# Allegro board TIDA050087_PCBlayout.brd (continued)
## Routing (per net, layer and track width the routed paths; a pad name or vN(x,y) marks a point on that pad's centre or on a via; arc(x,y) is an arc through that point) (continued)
N116698763: length 1
  TOP w0.104: U201.A8 v1(42.32,36.55)
  BOTTOM w0.112: R211.2 42.3,36.12 42.3,36.53 v1(42.32,36.55)
N116700633: length 6
  TOP w0.112: TP805.1 48.77,56.43 v1(49.19,56.86)
  BOTTOM w0.112: v1(49.19,56.86) 53.14,56.86 53.48,56.52 J802.51
N116701055: length 1.7
  TOP w0.254: U913.2 2.84,4.02 R1033.2
N116701070: length 1.5
  TOP w0.254: R1032.2 2.34,3.54 U913.1
N116772045: length 2.5
  TOP w0.381: 26.04,3.37 U919.2
N116772074: length 3
  TOP w0.203: U919.5 26.04,8.4 25.97,8.47 ; 25.97,8.47 R1088.1 26.14,8.63 R1087.2 ; 25.97,8.47 25.95,8.44 C719.2
N116772436: length 5.6
  TOP w0.112: R1089.2 10.01,16.63 v1(11.31,16.63) ; U920.3 10.5,19.04 10.42,19.12 R1090.1 10.5,19.45 10.51,19.46 v1(10.88,19.46)
  BOTTOM w0.112: v1(11.31,16.63) 11.31,17.89 10.9,18.3 10.9,19.44 v1(10.88,19.46)
N116861023: length 2.3
  BOTTOM w0.112: Q903.3 40.07,12.25 R717.1 40.44,10.89 R724.1
N116861029: length 2.8
  BOTTOM w0.112: Q902.3 35.95,10.01 35.95,8.85 35.66,8.55 R725.1 35.22,8.55 35.01,8.77 R719.1
N116892698: length 3.8
  TOP w0.112: TP969.1 24.85,20.84 v1(25.3,20.38) 26.17,19.51 U701.16
  BOTTOM w0.112: R1097.2 25.02,20.66 v1(25.3,20.38)
N116924893: length 5.1
  TOP w0.112: v1(32.52,14.08) 32.37,14.23 30.98,14.23 29.5,15.72 U701.1
  BOTTOM w0.112: R1091.1 33.16,14.87 32.52,14.23 v1(32.52,14.08)
N116924896: length 5.1
  TOP w0.112: v1(32.19,13.62) 32.19,13.65 31.91,13.93 31.74,13.93 31.74,13.93 30.95,13.93 29.57,15.31 29.56,15.31 29.33,15.54 U701.32
  BOTTOM w0.112: R1092.1 32.93,13.62 v1(32.19,13.62)
N116924899: length 4.6
  TOP w0.112: U701.24 25.26,16.07 24.62,15.42 24.62,14.49 25.02,14.08 v1(25.02,13.44)
  BOTTOM w0.112: v1(25.02,13.44) 24.59,13.01 24.59,12.8 R1093.1
N116925021: length 7.9
  TOP w0.112: v1(31.02,13.52) 29.47,15.07 28.81,15.07 28.8,15.08 28.79,15.08 28.57,15.3 U701.31
  BOTTOM w0.112: v1(31.02,13.52) 31.02,12.48 31.65,11.84 R1102.2 R1099.1
N116939248: length 4.9
  TOP w0.112: U701.8 29.68,18.87 30.11,19.31 v1(30.11,20.12)
  BOTTOM w0.112: v1(30.11,20.12) 30.17,20.18 R1064.2 30.17,21.03 30.82,21.67 32.02,21.67 R1094.2
N116980775: length 5.6
  TOP w0.112: U701.17 25.47,18.87 25.23,19.11 v1(25.23,19.79) 24.59,20.43 24.59,20.86 TP970.1
  BOTTOM w0.112: R1096.2 24.29,20.73 v1(25.23,19.79)
N116981199: length 1.7
  TOP w0.112: v1(24.97,7.63) 25.05,7.71 25.38,7.71 25.54,7.54 U919.6
  BOTTOM w0.112: R1098.1 24.51,7.63 v1(24.97,7.63)
N117032871: length 2.4
  TOP w0.381: U905.4 63.41,7.78 R1104.2 63.37,7.75 62.56,7.75 R1103.1

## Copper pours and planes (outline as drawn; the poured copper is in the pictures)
GND on TOP: 67.6,27.56 69.64,27.56 69.85,27.34 69.85,27.07 69.76,26.97 69.36,26.97 69.25,26.86 69.25,26.42 69.17,26.34 66.6,26.34 66.3,26.63 66.3,27.12 66.44,27.26 67.31,27.26
GND on TOP: 63.76,6.03 63.91,5.87 63.91,5.19 63.76,5.04 62.87,5.04 62.77,4.93 62.77,3.66 62.69,3.59 62.24,3.59 62.16,3.66 62.16,4.78 61.88,5.06 58.02,5.06 57.84,5.24 57.84,5.95 57.92,6.03
GND on TOP: 53.15,40.42 54.8,40.42 54.89,40.33 54.89,40.02 54.79,39.92 54.55,39.92 54.35,39.73 54.35,37.85 54.87,37.33 54.87,37.14 54.73,37 53.22,37 53.09,37.12 53.09,37.31 53.21,37.43 53.8,37.43 53.98,37.61 53.98,39.03 53.91,39.09 53.91,39.24 53.96,39.29 53.96,39.8 53.98,39.81 53.98,39.86 53.87,39.96 53.22,39.96 53.15,40.03
GND on TOP: 62.26,11.85 64.6,11.85 64.76,11.7 64.76,7.75 64.76,7.74 64.59,7.57 63.92,7.57 63.86,7.63 63.86,8.14 63.68,8.31 62.81,8.31 62.68,8.44 62.68,10.23 62.22,10.69 62.22,11.81
GND on TOP: 8.59,11.38 12.2,11.38 12.52,11.06 12.52,9.64 12.17,9.29 8.67,9.29 8.35,9.61 8.35,11.13
GND on TOP: 26.7,22.89 28.38,22.89 28.76,22.51 28.76,21.55 28.71,21.5 26.73,21.5 26.55,21.67 26.55,22.74
GND on TOP: 50.71,40.44 52.3,40.44 52.34,40.39 52.34,40.11 52.3,40.06 51.68,40.06 51.47,39.85 51.47,37.59 51.62,37.43 52.15,37.43 52.31,37.27 52.31,37.08 52.25,37.01 50.78,37.01 50.61,37.18 50.61,37.34 50.74,37.47 51,37.47 51.13,37.59 51.13,39.76 50.94,39.95 50.66,39.95 50.58,40.04 50.58,40.31
GND on TOP: 2.69,8.09 3.96,8.09 4.75,7.3 4.75,4.89 4.31,4.45 3.79,4.45 3.71,4.54 3.71,5.38 3.57,5.52 1.85,5.52 1.69,5.68 1.69,6.96 1.95,7.21 2.45,7.21 2.64,7.4 2.64,8.04
GND on TOP: 0.49,60.6 73.23,60.6 73.23,50.85 71.69,50.85 65.18,57.37 61.75,57.37 59.02,60.09 41.84,60.09 40.07,58.33 38.66,58.33 36.87,60.12 11.79,60.12 10.89,59.21 8.21,59.21 7.32,60.1 7.32,60.12 2.63,60.12 1.19,58.67 1.19,51.47 1.89,50.77 1.89,46.98 1.19,46.29 1.19,26.31 1.86,25.64 1.86,22.49 1.02,21.65 1.02,12.3 1.61,11.72 1.61,8.24 1.19,7.82 1.19,1.8 1.11,1.71 3.52,1.71 3.84,2.04 5.33,2.04 5.89,2.6 5.89,3.45 5.92,3.48 7.49,3.48 8.16,2.81 8.16,0.51 0.49,0.51
GND on TOP: 48.09,42.93 52.27,42.93 52.39,42.81 52.39,42.61 52.28,42.5 49.16,42.5 48.98,42.32 48.98,35.05 49.13,34.9 50.27,34.9 50.34,34.83 50.34,34.48 50.31,34.45 48.62,34.45 48.45,34.62 48.45,42.35 48.27,42.53 48.07,42.53 48,42.6 48,42.83
GND on TOP: 20.83,12.2 20.83,12.83 21.21,13.22 22.15,13.22 22.79,13.85 24.64,13.85 24.69,13.8 24.69,12.1 24.54,11.95 21.09,11.95
GND on TOP: 27.84,7.32 27.87,7.35 27.87,7.47 27.9,7.5 29.22,7.5 29.27,7.45 29.27,6.38 29.24,6.36 27.9,6.36 27.87,6.33 27.03,6.33 27.01,6.36 25.74,6.36 25.71,6.33 25.71,5.54 25.66,5.49 25.28,5.49 25.15,5.62 23.6,5.62 23.5,5.72 23.5,7.27 23.63,7.4 24.64,7.4 25.15,6.89 27.64,6.89 27.84,7.09
GND on TOP: 30.87,11.95 31.37,11.44 33.23,11.44 33.23,11.46 33.46,11.69 33.46,13.14 33.37,13.23 29.69,13.23 29.55,13.09 29.55,12.07 29.67,11.95
GND on TOP: 25.56,20.58 25.56,20.17 25.91,19.82 26.32,19.82 26.37,19.77 26.7,19.77 26.75,19.82 26.75,19.95 26.14,20.56 26.07,20.56 25.96,20.66 25.96,21.17 25.56,21.17 25.51,21.11 25.51,20.63
GND on TOP: 41.4,13.53 41.84,13.09 41.84,12.3 41.1,11.56 35.87,11.56 35.49,11.95 35.49,13.47 35.55,13.53
GND on TOP: 66.8,23.43 68.84,23.43 69,23.27 69.95,23.27 70.18,23.04 70.18,19.63 69.97,19.43 68.9,19.43 68.56,19.77 68.56,21.02 68.16,21.43 67.06,21.43 66.74,21.75 66.74,23.36
GND on TOP: 72.23,17.68 73.23,17.68 73.23,0.51 69.15,0.51 68.76,0.9 68.76,14.46 69.14,14.84 69.87,14.85 71.36,14.85 71.76,15.25 71.76,15.83 71.8,15.87 71.8,17.26
GND on TOP: 12.66,20.12 12.66,18.75 12.55,18.65 11.49,18.65 10.93,18.09 10.61,18.41 11.11,18.9 11.11,19.21 11.21,19.31 11.21,19.72 11.08,19.84 10.65,19.84 10.62,19.82 10.19,19.82 10.08,19.7 10.08,19.1 9.78,18.8 8.9,18.8 8.62,19.08 8.62,20.3 9.01,20.7 12.08,20.7
GND on BOTTOM: 23.4,15.91 23.37,15.91 23.25,16.03 22.36,16.03 21.75,15.42 21.75,15.4 21.72,15.37 21.72,14.28 21.93,14.08 23.22,14.08 23.4,14.26
GND on BOTTOM: 0.49,60.6 73.23,60.6 73.23,45.89 66.86,45.89 65.42,44.46 65.42,44.18 64.17,44.18 63.32,45.04 60.87,45.04 59.75,43.91 59.75,43.29 59.12,42.67 58.08,42.67 56.83,43.91 55.43,43.91 54.08,45.27 54.08,50.55 55.2,51.68 58.5,51.68 60.56,53.74 60.56,58.51 59.06,60.01 43.04,60.01 40.72,57.69 39.17,57.69 39,57.86 33.06,57.86 32.79,58.13 21.99,58.13 18.45,54.6 12.86,54.6 12.57,54.89 8.71,54.89 8.72,54.89 12.57,54.89 12.7,54.75 12.79,54.75 12.87,54.74 12.95,54.69 13.04,54.6 13.08,54.6 13.12,54.63 13.11,54.68 12.31,55.49 11.68,55.49 7.36,59.82 6.71,59.82 6.71,59.73 6.75,59.72 6.81,59.69 6.86,59.64 6.92,59.62 6.99,59.63 7.08,59.68 7.19,59.7 7.42,59.6 7.52,59.37 7.47,59.19 7.33,59.07 7.3,59.05 7.3,58.67 7.83,58.13 7.88,58.06 7.9,57.97 7.9,55.43 8.54,54.79 8.59,54.78 8.62,54.81 8.63,54.82 8.63,53.37 13.27,48.73 13.27,46.17 12.84,45.74 7.15,45.74 5.36,43.95 2.3,43.95 0.49,45.75
GND on BOTTOM: 28.83,5.24 28.73,5.14 25.05,5.14 24.82,5.37 24.82,5.39 24.8,5.42 24.8,7.02 25.46,7.68 26.17,7.68 26.19,7.65 26.19,7.04 26.9,6.33 28.73,6.33 28.83,6.23
GND on BOTTOM: 62.7,11.51 62.7,7.92 62.77,7.85 64.02,7.85 64.08,7.91 64.08,11.44 63.92,11.61 62.8,11.61
GND on BOTTOM: 66.35,27.54 69.99,27.54 70.18,27.36 70.18,26.4 69.93,26.15 66.37,26.15 66.17,26.35 66.17,27.36
GND on BOTTOM: 66.81,3.42 67.25,3.42 68.27,4.44 68.27,5.51 68.46,5.7 68.46,13.14 69.53,14.21 69.6,14.21 69.83,14.43 71.25,14.43 71.51,14.69 71.51,16.57 72.07,17.13 72.9,17.13 73.21,16.82 73.21,0.69 73.03,0.52 65.51,0.52 65.31,0.72 65.31,1.92
GND on BOTTOM: 0.49,41.91 6.92,41.91 7.5,41.33 7.5,38.24 5.52,36.26 5.52,34.22 7.5,32.24 7.5,4.06 8.29,3.27 8.29,0.51 0.49,0.51
GND on L2_GND_1: 0.5,60.6 73.23,60.6 73.23,0.51 0.5,0.51
GND on L3_INT_1: outline of 85 points within 0.49,0.51 73.23,60.6 ; 1 cut-out
GND on L4_PWR: 35.44,60.6 73.23,60.6 73.23,25.33 69.54,25.33 68.93,25.94 68.93,34.33 67.88,35.38 67.88,43.36 65.59,45.65 44.94,45.65 43.89,46.7 43.89,49.41 42.95,50.35 35.77,50.35 35,51.12 35,60.15
GND on L5_GND_2: 0.5,60.6 73.23,60.6 73.23,59.97 73.23,59.97 73.23,55.26 73.23,55.26 73.23,0.51 0.5,0.51
VDD2_DDR on TOP: 21.39,28.2 21.29,28.3 21.29,28.91 20.88,29.32 20.88,30.33 20.77,30.45 20.75,30.45 20.29,30.91 19.44,30.91 18.96,31.39 18.96,32.4 19.2,32.63 22.01,32.63 22.62,32.02 22.62,28.31 22.51,28.2
VDD2_DDR on TOP: 50.69,39.38 50.95,39.38 51.01,39.32 51.01,37.71 50.84,37.54 50.65,37.54 50.52,37.41 50.52,37.07 50.66,36.93 50.88,36.93 50.92,36.9 50.92,36.52 50.84,36.44 50.45,36.44 50.35,36.35 50.35,36.08 50.23,35.97 49.57,35.97 49.53,36.01 49.53,36.3 49.71,36.48 49.78,36.48 50,36.7 50,38.74 50.11,38.84 50.5,38.84 50.57,38.91 50.57,39.27
VDD2_DDR on BOTTOM: 50.6,39.36 50.88,39.36 50.96,39.28 50.96,37.62 50.92,37.57 50.77,37.57 50.76,37.58 50.62,37.58 50.5,37.46 50.5,37.1 50.68,36.92 51.33,36.92 51.42,36.84 51.42,36.55 51.32,36.45 50.61,36.45 50.61,36.45 50.54,36.45 50.38,36.29 50.38,36 50.34,35.97 49.66,35.97 49.54,35.84 49.54,35.67 49.37,35.5 49.12,35.5 49.06,35.57 49.06,35.86 49.14,35.95 49.26,35.95 49.49,36.17 49.49,36.39 49.59,36.5 49.94,36.5 49.98,36.54 49.98,37.39 49.91,37.47 49.91,37.89 50.04,38.02 50.04,38.38 50.12,38.46 50.42,38.46 50.53,38.58 50.53,39.3
VDD2_DDR on L4_PWR: 50.73,39.36 50.95,39.36 51.07,39.23 51.07,38.33 51.51,37.9 51.51,25.17 49.28,22.94 41.53,22.94 41.3,23.17 38.74,23.17 36.89,21.32 33.38,21.32 32.59,22.11 28.53,22.11 28.28,22.36 28.28,24.67 26.37,26.58 24.14,26.58 24.11,26.55 17.63,26.55 16.69,27.49 16.69,30.72 18.1,32.13 21.88,32.13 22.2,31.81 22.2,29.6 22.71,29.1 31.02,29.1 31.25,28.87 31.25,26.56 31.95,25.86 45.11,25.86 46.52,27.27 46.52,38.37 47.03,38.88 50.46,38.88 50.56,38.98 50.56,39.19
VDD_1P8 on TOP: 22.82,5.67 23.39,5.1 24.43,5.1 24.75,4.78 24.75,4.66 24.77,4.66 24.77,1.63 24.57,1.43 21.77,1.43 21.34,1.86 21.34,5.77 21.55,5.98 21.55,6.36 20.48,7.42 20.48,10.34 20.68,10.55 21.32,10.55 21.49,10.37 21.49,9.63 21.75,9.38 21.8,9.38 21.82,9.36 24.77,9.36 25.21,9.8 25.45,9.8 25.46,9.81 25.58,9.81 25.66,9.74 25.66,9.38 25.33,9.05 24.82,9.05 24.57,8.8 24.57,8 24.46,7.89 23.48,7.89 22.82,7.22
VDD_1V8 on TOP: 60.7,11.91 61.66,11.91 61.88,11.68 61.88,10.75 62.21,10.42 62.21,8.7 62.11,8.59 60.77,8.59 60.67,8.69 60.67,11.88
VDD_1V8 on TOP: 15.25,4.73 14.89,4.38 13.85,4.38 13.72,4.5 13.72,5.32 14.17,5.76 14.43,5.76 14.79,6.12 14.79,7.47 14.48,7.78 14.48,8.39 14.59,8.49 16.67,8.49 17.18,9 17.18,10.37 17.3,10.5 17.3,11.69 17.02,11.97 17.02,12.15 17.15,12.28 19.41,12.28 19.58,12.44 20.35,12.44 20.55,12.24 20.55,11.13 20.35,10.93 20,10.93 19.44,10.37 19.44,7.37 19.67,7.19 19.89,6.97 20.1,6.97 21.16,5.9 21.16,5.67 20.96,5.47 20.17,5.47 18.93,6.71 16.72,6.71 15.25,5.24
VDD_1V8 on BOTTOM: 61.1,11.58 62.34,11.58 62.51,11.41 62.51,7.96 62.41,7.85 61.18,7.85 61.08,7.96 61.08,11.56
VDD_1V8 on L3_INT_1: 54.3,28 56.82,28 64.49,20.33 64.49,6.86 62.11,4.48 49.8,4.48 46.61,7.66 46.61,9.76 45.75,10.62 43.65,10.62 38.14,16.14 29.85,16.14 28.96,17.03 28.96,17.61 28.78,17.79 26.42,17.79 25.99,17.36 25.99,16.69 23.63,14.33 23.63,12.61 21.57,10.55 21.57,10.19 21.14,9.76 19.16,9.76 18.81,10.1 18.81,14.7 20.19,16.07 20.19,16.78 22.26,18.85 22.26,20.28 23.73,21.75 29.47,21.75 31.49,19.73 40.79,19.73 52.05,8.46 59.74,8.46 60.67,9.4 60.67,15.23 59.84,16.05 55.27,16.05 55.24,16.09 54.29,16.09 53.78,16.59 53.78,27.48
VDD_3P3 on TOP: 33.15,11.08 33.25,10.98 33.25,9.51 31.3,7.55 31.3,6.64 31.16,6.5 31.16,5.57 31.64,5.09 32.42,5.09 32.82,4.68 32.82,3.94 32.54,3.66 29.62,3.66 29.43,3.86 29.43,4.16 29.57,4.3 29.57,7.5 28.89,8.19 28.89,9.23 27.56,10.55 27.56,11.31 27.7,11.45 30.89,11.45 31.26,11.08
VDD_3V3 on TOP: 39.33,2.75 39.32,2.76 35.78,2.76 35.64,2.62 33.31,2.62 33.2,2.72 32.04,2.72 32.04,2.6 29.75,2.6 29.55,2.39 29.55,1.89 29.93,1.51 29.93,1.38 30.31,1 40.57,1 40.93,1.35 40.93,2.47 40.62,2.78 40.16,2.78 40.14,2.75
VDD_3V3 on TOP: 66.78,25.41 70.06,25.41 70.35,25.12 70.35,23.7 70.23,23.58 66.8,23.58 66.62,23.76 66.62,25.24
VDD_3V3 on BOTTOM: 35.18,2.78 41.69,2.78 41.79,2.67 41.79,1.86 41.74,1.81 31.81,1.81 31.53,2.09 31.53,3.11 34.85,3.11
VDD_3V3 on BOTTOM: 70.29,25.56 70.57,25.28 70.57,23.88 70.4,23.71 68.87,23.71 68.63,23.47 68.63,19.65 66.92,17.94 55.51,17.94 55.22,18.23 55.22,18.63 55.23,18.63 55.3,18.7 56.17,18.7 56.44,18.97 56.44,19.85 57.6,21.01 57.6,21.87 57.92,22.19 62.27,22.19 65.65,25.56
VDD_3V3 on L4_PWR: 68.18,24.93 71.39,24.93 71.4,24.92 73.23,24.92 73.23,1.33 72.41,0.51 32.81,0.51 32.81,1.65 34.36,3.2 36.44,3.2 36.48,3.16 40.87,3.16 41.87,2.17 43.9,2.17 44.08,2.17 46.31,2.17 47.58,3.44 47.58,5.62 47.96,6 48.88,6 49.78,6.9 67.94,6.9 68.82,7.79 68.82,22.69 67.98,23.53 67.98,24.72
VDD_ANA_0P8 on TOP: 19.1,21.52 19.1,19.23 19.09,19.22 19.09,19.04 18.93,18.88 16.97,18.88 16.85,19.01 16.85,21.88 17.06,22.09 18.54,22.09
VDD_ANA_0P8 on L3_INT_1: 51.12,41.39 54.48,41.39 55.38,40.5 55.38,37.29 54.6,36.51 49.51,36.51 47.39,34.39 47.39,27.12 44.74,24.47 22.75,24.47 19.56,21.28 19.56,21.28 19.08,20.8 17.49,20.8 16.91,21.38 16.91,23.55 21.54,28.17 41.19,28.17 42.57,29.56 42.57,34.92 46.71,39.06 47.06,39.06 48.11,40.11 49.3,40.11 49.48,39.93 50.32,39.93 50.82,40.43 50.82,41.1
VDD_ANA_0V8 on TOP: 23.32,21.27 23.88,21.27 24.39,20.76 24.39,19.92 24.34,19.87 23.96,19.87 23.93,19.9 23.93,20.4 23.75,20.58 22.48,20.58 22.36,20.45 22.36,20.44 22.35,20.44 22.09,20.19 22.09,19.63 21.84,19.37 21.61,19.37 21.6,19.36 21.55,19.36 21.37,19.54 20.91,19.54 20.86,19.49 20.86,19.06 20.63,18.83 19.84,18.83 19.64,19.03 19.64,21.57 19.96,21.89 19.98,21.89 20.28,22.18 22.41,22.18
VDD_ANA_1P8 on TOP: 9.38,8.92 12.08,8.92 12.18,8.83 12.18,5.8 12.03,5.65 10.65,5.65 10.4,5.9 8.95,5.9 8.79,6.05 8.79,6.74 8.05,7.49 8.05,8.2 8.75,8.91 9.36,8.91
VDD_ANA_1P8 on L4_PWR: 51.08,45.41 65.2,45.41 68.59,42.01 68.59,26.02 67.7,25.13 67.7,23.31 68.59,22.41 68.59,12.78 68.11,12.3 64.45,12.3 63.96,11.82 63.96,8.07 63.84,7.94 49.32,7.94 47.9,9.37 47.9,11.45 47.76,11.59 42.53,11.59 40.26,9.33 40.26,8.36 40.04,8.14 37.9,8.14 36.86,7.09 36.86,6.95 33.91,3.99 33.03,3.99 32.85,3.82 32.85,3.11 30.89,1.15 11.74,1.15 11,1.89 9.96,1.89 9.93,1.91 9.93,7.58 10.39,8.04 10.5,8.04 10.53,8.07 23.98,8.07 24.67,8.76 24.67,11.08 24.77,11.18 31.63,11.18 32.09,11.64 32.09,13.06 33.51,14.49 36.76,14.49 37.21,14.94 56.81,14.94 63.65,21.77 63.65,39.13 62.14,40.64 57.21,40.64 56.62,40.05 54.03,40.05 53.55,40.53 51.6,40.53 51.13,40.99 50.65,40.99 50.52,41.13 50.52,41.59 50.81,41.88 50.81,45.14
VDD_ANA_1V8 on TOP: 12.02,5.06 12.41,5.44 13.29,5.44 13.43,5.3 13.43,4.35 12.63,3.55 12.63,2.29 12.43,2.09 11.79,2.09 10.53,3.35 9.21,3.35 8.67,3.89 8.67,4.6 8.97,4.91 10.37,4.91 10.52,5.06
VDD_SOC on TOP: 40.59,20.43 40.59,20.15 40.43,19.98 38.09,19.98 38.05,20.02 38.05,21.86 38.05,21.86 38.05,23.26 38.2,23.41 41.6,23.41 41.81,23.2 41.81,22.89 41.53,22.61 41.53,21.37
VDD_SOC on TOP: 51.59,39.85 51.97,39.85 52.06,39.94 52.34,39.94 52.47,40.07 52.47,40.29 52.53,40.35 52.91,40.35 52.97,40.29 52.97,40.04 53.16,39.85 53.78,39.85 53.88,39.76 53.88,37.66 53.79,37.58 53.14,37.58 53.05,37.49 53.05,37.09 52.99,37.02 52.58,37.02 52.44,37.17 52.44,37.33 52.19,37.58 51.69,37.58 51.53,37.73 51.53,39.79
VDD_SOC on BOTTOM: 53.54,39.86 53.86,39.86 53.92,39.79 53.92,39.43 53.83,39.33 53.83,39.03 53.95,38.91 53.95,38.39 53.89,38.33 53.89,38.11 53.76,37.99 52.99,37.99 52.89,37.89 52.89,37.06 52.79,36.95 52.59,36.95 52.49,37.05 52.49,37.33 52.39,37.43 52.39,37.93 52.24,38.09 51.7,38.09 51.51,38.28 51.51,38.92 51.66,39.07 51.66,39.86 51.76,39.96 52.2,39.96 52.56,40.32 52.88,40.32 52.94,40.27 52.94,39.42 53,39.35 53.38,39.35 53.48,39.45 53.48,39.79
VDD_SOC on L4_PWR: 53.34,40.4 53.78,39.96 57.05,39.96 57.18,40.09 61.91,40.09 63.05,38.95 63.05,22.26 56.11,15.32 47.02,15.32 46.56,15.78 46.56,18.78 45.75,19.59 38.46,19.59 38.26,19.79 38.26,22.1 38.83,22.68 38.84,22.68 38.96,22.79 41.14,22.79 41.26,22.68 49.38,22.68 51.8,25.1 51.8,37.52 51.79,37.53 51.79,37.97 51.29,38.47 51.29,38.93 51.38,39.02 51.38,39.41 52.36,40.4
VDD_SOC_0V85 on TOP: 45.78,17.76 45.78,18.78 45.75,18.8 43.11,18.8 43.06,18.75 42.45,18.75 42.22,18.98 35.95,18.98 34.22,17.25 34.22,14.59 34.68,14.13 44.2,14.13 44.62,14.55 44.62,17.5 44.71,17.58 45.6,17.58
VDD_SOC_0V85 on BOTTOM: 43.06,18.85 43.06,17.71 45.83,17.71 45.83,18.85
VDD_SOC_0V85 on L4_PWR: 45.88,18.96 35.57,18.96 33.79,17.18 33.79,15.32 34.25,14.87 36.66,14.87 37.09,15.3 45.98,15.3 46.08,15.4 46.08,18.75
VDD_USB_3P3 on TOP: 36.89,3.23 36.67,3 35.9,3 35.78,3.12 34.85,3.12 34.58,3.39 34.58,3.87 35.41,4.71 36.45,4.71 36.89,4.27
VDDQ_DDR on TOP: 50.13,41.44 50.83,41.44 50.9,41.38 50.9,40.62 50.81,40.53 50.61,40.53 50.5,40.43 50.5,39.97 50.65,39.82 50.76,39.82 50.84,39.74 50.84,39.62 50.52,39.3 50.52,39.03 50.44,38.95 50.21,38.95 50.06,39.11 50.06,41.3 50.13,41.38
VDDQ_DDR on TOP: 33.22,31.7 34.74,31.7 35.06,31.38 35.06,31.38 35.06,29.9 33.87,28.71 33.87,28 33.62,27.74 32.64,27.74 31.91,28.48 31.88,28.48 31.88,30.2 32.13,30.45 32.13,30.92 32.19,30.98 32.5,30.98
VDDQ_DDR on L4_PWR: 50.37,41.62 50.37,41.13 50.58,40.91 50.88,40.91 50.93,40.86 50.93,39.96 50.48,39.5 50.48,39.1 50.34,38.96 46.89,38.96 46.28,38.35 46.28,27.55 44.77,26.04 32.13,26.04 31.52,26.64 31.52,28.71 31.98,29.16 41.74,29.16 42.12,29.54 42.12,34.43 42.49,34.81 43.31,34.81 43.75,35.25 43.75,36.35 43.74,36.37 43.74,44.91 44.2,45.38 50.42,45.38 50.57,45.23 50.57,41.82
BB_VSYS_5V on TOP: 65.17,11.74 66.97,11.74 67.47,11.25 67.47,3.16 65.89,1.58 47.86,1.58 47.78,1.66 47.78,3.63 46.78,4.63 46.78,7.48 46.67,7.6 45.27,7.6 45.17,7.5 45.17,6.97 43.47,5.27 43.15,4.78 42.55,4.78 42.37,4.96 42.37,6.87 42.42,6.92 42.42,6.94 42.6,7.12 43.61,7.12 43.89,7.4 43.89,8.21 44.25,8.58 44.25,8.58 44.32,8.64 44.33,8.64 44.35,8.67 48.6,8.67 49.41,7.86 49.41,5.6 50.25,4.76 50.25,4.45 50.37,4.33 50.81,4.33 51.16,4.68 61.85,4.68 61.91,4.63 61.91,3.56 62.03,3.44 62.92,3.44 63.02,3.54 63.02,4.63 63.06,4.67 63.98,4.67 64.5,5.19 64.5,6.89 64.5,6.89 65.04,7.42 65.04,11.61
BB_VSYS_5V on BOTTOM: 64.29,11.64 65.92,11.64 66.09,11.47 66.09,10.66 66.2,10.55 66.37,10.55 66.56,10.36 66.56,8.85 66.53,8.82 66.17,8.82 66.1,8.74 66.1,8.68 66.09,8.68 66.09,7.89 66.1,7.86 66.16,7.79 66.16,3.5 64.86,2.2 64.86,1.11 64.37,0.62 59.82,0.62 59.14,1.3 59.14,3.28 60.51,4.66 62.62,4.66 64.29,6.33
BB_VSYS_5V on L4_PWR: 64.93,11.89 68.15,11.89 68.41,11.64 68.41,7.78 68.05,7.42 64.78,7.42 64.5,7.7 64.5,11.46
BB_VSYS_5V on L4_PWR: 47.55,9.18 48.82,7.91 48.82,7.17 48.27,6.61 44.56,6.61 43.66,7.51 43.66,8.81 44.02,9.18
LPD4/X_VDD1 on TOP: 16.64,9.94 16.64,9.14 16.48,8.98 15.24,8.98 13.84,10.37 13.84,11.82 13.85,11.82 14.28,12.25 16.01,12.25 16.26,12 16.31,12 16.36,11.95 16.36,10.22
LPD4/X_VDD1 on BOTTOM: 37.3,42.97 38.97,42.97 39.17,42.77 39.17,41.01 39.65,40.53 39.65,38.95 40.05,38.56 40.05,36.28 39.36,35.59 39.36,31.89 39.15,31.67 22.68,31.67 21.01,33.34 21.01,36.84 21.21,37.03 25.19,37.03 26.17,38.01 26.17,42.6 27.8,44.23 32.36,44.23 33.14,43.45 33.14,36.36 33.96,35.54 34.5,35.54 34.94,35.1 36.73,35.1 37.27,35.65 37.27,42.69 37.21,42.75 37.21,42.87 ; 1 cut-out
LPD4/X_VDD1 on L3_INT_1: 23.62,43.45 32.09,43.45 33.14,42.4 33.14,33.87 34.11,32.9 38.94,32.9 39.12,32.73 39.12,31.42 38.87,31.17 23.37,31.17 20.92,33.62 20.92,40.75
LPD4/X_VDD1 on L4_PWR: 13,38.61 21.41,38.61 22.13,37.89 22.13,33.29 22.11,33.28 22.11,32.72 21.82,32.43 17.78,32.43 16.39,31.04 16.39,28.2 16.01,27.82 14.36,27.82 13.98,27.44 13.98,17.13 16.24,14.87 16.24,9.26 15.45,8.47 10.36,8.47 9.98,8.84 9.98,35.59
LPD4/X_VDD2 on TOP: 23.95,28.14 23.78,28.3 23.78,31.27 24.28,31.77 26,31.77 26.89,30.88 26.89,28.47 26.78,28.35 25.56,28.35 25.34,28.14
LPD4/X_VDD2 on L4_PWR: 43.58,35.47 43.17,35.06 42.44,35.06 42.07,35.43 42.07,41.48 41.31,42.23 39.66,42.23 38.26,40.84 38.26,40.04 38.87,39.43 38.89,39.43 39.2,39.12 39.2,36.79 38.31,35.9 38.31,32.5 38.02,32.21 32.42,32.21 32.11,32.52 32.11,34.3 31,35.41 31,39.5 31.98,40.47 31.98,42.95 31.61,43.32 28.92,43.32 28.28,42.68 28.28,29.62 28.04,29.38 22.83,29.38 22.42,29.78 22.42,44.86 23.58,46.02 26.78,46.02 30.83,50.07 42.78,50.07 43.58,49.28
LPD4/X_VDD2_1V1 on TOP: 16.8,28.76 17.25,29.22 20.61,29.22 20.96,28.86 20.96,28.23 21.6,27.59 25.28,27.59 25.43,27.44 26.78,27.44 26.98,27.24 26.98,26.3 26.88,26.19 26.88,25.18 26.8,25.1 25.89,25.1 25.58,25.41 20.71,25.41 20.2,25.92 20.2,27.95 20.07,28.07 19.06,28.07 19.06,27.57 18.93,27.44 18.8,27.44 18.67,27.57 18.67,28.07 16.9,28.07 16.13,27.31 16.13,25.92 16.01,25.79 15.25,25.79 14.61,26.42 14.61,28.73 14.78,28.9 15.47,28.9 15.61,28.76
LPD4/X_VDD2_1V1 on TOP: 21.19,11.44 26.85,11.44 27.01,11.28 27.01,10.52 26.65,10.17 25.3,10.17 24.67,9.53 21.93,9.53 21.72,9.74 21.72,10.5 21.39,10.83 21.21,10.83 21.04,11.01 21.04,11.28
LPD4/X_VDD2_1V1 on L4_PWR: 24.24,12.43 24.24,8.97 23.78,8.52 18.8,8.52 17.13,10.19 17.13,14.59 14.36,17.36 14.36,25.53 15.02,26.19 25.86,26.19 27.16,24.9 27.16,22.66 26.7,22.21 22.18,22.21 21.75,21.77 21.75,14.92
LPD4/X_VDDQ on TOP: 31.17,27.75 30.3,27.75 30.3,27.74 30.13,27.91 30.13,27.95 30.08,28 29.78,28.3 28.5,28.3 28.38,28.43 28.38,30.59 28.53,30.74 28.58,30.74 28.58,30.75 28.73,30.9 31.21,30.9 31.3,30.8 31.3,27.88
LPD4/X_VDDQ on L4_PWR: 39.75,42.07 41.22,42.07 41.9,41.38 41.9,29.8 41.44,29.34 28.97,29.34 28.56,29.75 28.56,42.6 29.08,43.12 31.38,43.12 31.59,42.91 31.59,40.54 30.79,39.74 30.79,35.32 31.93,34.19 31.93,32.25 32.16,32.02 38.18,32.02 38.48,32.31 38.48,35.82 39.44,36.79 39.44,39.1 38.44,40.1 38.44,40.76
LPD4/X_VDDQ_0V6 on TOP: 28.48,27.29 35.26,27.29 35.73,27.76 35.73,28.41 35.94,28.62 38.86,28.62 38.89,28.59 40.01,28.59 40.46,28.14 40.46,27.13 40.17,26.84 38.92,26.84 38.77,26.99 38.77,27.34 38.66,27.44 37.85,27.44 37.78,27.36 37.78,26.93 37.68,26.84 37.31,26.84 37.27,26.88 37.27,27.36 37.17,27.46 36.38,27.46 36.28,27.36 36.28,26.89 36.23,26.84 36.23,26.8 35.62,26.19 35.62,25.97 34.63,24.98 27.65,24.98 27.4,25.23 27.4,27.12 27.86,27.59 28.17,27.59
NVCC_1P8 on TOP: 13.61,9.14 13.61,8.44 13.72,8.32 14.02,8.32 14.15,8.19 14.15,7.65 13.75,7.25 13.75,5.96 13.57,5.79 12.66,5.79 12.42,6.02 12.42,9.25 12.58,9.41 13.34,9.41
NVCC_1P8 on TOP: 16.77,34.25 16.77,33.07 16.52,32.83 15.4,32.83 15.33,32.89 15.33,33.57 14.93,33.97 13.59,33.97 13.43,33.81 13.43,32.95 13.3,32.83 12.19,32.83 11.87,33.15 11.87,35.46 12.55,36.14 14.87,36.14
NVCC_1P8 on BOTTOM: 52.63,36.88 53.23,36.88 53.49,36.62 53.49,29.02 48.25,23.78 45.27,23.78 44.63,24.42 43.43,24.42 40.57,27.28 21,27.28 15.64,32.65 15.64,33.91 16.13,34.4 16.49,34.4 22.64,28.25 43.67,28.25 50.26,34.84 51.01,34.84 51.01,34.83 51.22,34.62 51.22,33.11 45.13,27.02 45.13,25.08 45.93,24.28 46.46,24.28 46.63,24.45 46.63,24.94 46.01,25.56 46.01,26.08 52.68,32.75 52.68,35.05 52.56,35.16 52.58,35.18 52.58,36.75 52.54,36.79
NVCC_1P8 on L3_INT_1: 9.24,34.38 12.44,34.38 12.79,34.03 12.79,30.92 11.22,29.36 11.22,24.97 8.65,22.4 8.65,18.57 10.19,17.03 10.19,11.69 13.28,8.61 13.28,6.95 12.97,6.64 10.03,6.64 8.56,8.12 8.56,16.1 6.81,17.85 6.81,24.25 8.86,26.3 8.86,34.01
NVCC_3P3 on TOP: 41.22,4.82 41.38,4.66 41.38,3.58 41.1,3.3 38.1,3.3 37.79,2.99 37.34,2.99 37.2,3.13 37.2,3.78 37.22,3.8 37.22,4.25 37.79,4.82
NVCC_AON on BOTTOM: 60.91,44.55 62.43,44.55 62.66,44.33 62.66,41.91 58.27,37.51 55.29,37.51 55.03,37.77 55.03,38.41 55.14,38.52 56.63,38.52 60.5,42.39 60.5,44.15
NVCC_BBSM_1P8 on TOP: 19.37,12.77 19.06,12.46 17.18,12.46 17.06,12.58 17.06,13 17.12,13.06 17.12,13.9 17.38,14.16 18.45,14.16 18.78,14.49 18.78,14.79 18.67,14.89 18.67,16.14 18.8,16.26 19.44,16.26 19.54,16.36 19.84,16.36 19.97,16.24 19.97,15.86 20.07,15.76 20.07,14.84 20.5,14.41 20.5,12.99 20.29,12.77
NVCC_BBSM_1V8 on TOP: 12.72,17.65 13.93,16.44 14.66,16.44 14.74,16.52 14.74,17.15 14.86,17.28 14.99,17.28 15.12,17.15 15.12,16.52 15.2,16.44 16.19,16.44 17.02,17.28 17.02,18.3 17.28,18.55 20.2,18.55 20.57,18.18 20.55,18.17 20.55,17.08 20,16.52 18.42,16.52 18.26,16.35 17.32,16.35 17.23,16.26 17.23,16.09 16.57,15.42 13.11,15.42 11.13,17.41 11.13,18.04 11.42,18.33 12.72,18.33
NVCC_BBSM_1V8 on L3_INT_1: 33.07,59.9 34.72,58.25 34.72,50.93 33.98,50.18 31.12,50.18 29.03,52.26 23.07,52.26 19.95,55.39 19.95,57.82 18.69,59.08 15.59,59.08 12.2,55.68 12.2,41.71 12.33,41.57 12.33,40.32 11.98,39.97 9.58,39.97 8.62,40.93 8.62,58.46 10.05,59.9
NVCC_GPIO on BOTTOM: 55.17,37.42 58.54,37.42 63.9,32.06 63.9,27.92 65.65,26.17 66.08,26.17 66.24,26.01 67.15,26.01 67.24,25.92 67.24,25.62 67.22,25.6 64.17,25.6 62.28,27.48 62.28,31.61 58.04,35.85 56.1,35.85 55.07,36.88 55.07,37.33
NVCC_SD on TOP: 25.56,24.92 27.29,24.92 27.45,24.76 29.25,24.76 29.72,24.29 29.72,23.63 29.24,23.15 26.37,23.15 25.84,22.61 25.53,22.61 25.41,22.74 25.41,23.55 25.51,23.65 25.51,24.87
NVCC_SD2 on TOP: 21.85,23.48 23.07,24.7 24.9,24.7 25.1,24.49 25.1,22.92 24.72,22.54 22.23,22.54 21.85,22.92
NVCC_SD2 on TOP: 66.87,32.04 67.94,32.04 68.22,31.76 68.22,29.82 67.49,29.09 65.81,29.09 65.56,29.33 65.56,29.9 66.04,30.38 66.04,31.37 66.14,31.47 66.62,31.47 66.74,31.59 66.74,31.91
NVCC_SD2 on BOTTOM: 54.61,36.82 54.97,36.82 56.2,35.59 58.16,35.59 62.1,31.65 62.1,26.94 59.91,24.75 54.12,24.75 51.54,22.16 44.15,22.16 43.73,22.58 43.73,23.89 44.05,24.21 44.61,24.21 45.42,23.4 49.01,23.4 54.55,28.94 54.55,36.75
S1_CPU_VDD2_DDR on TOP: 18.11,32.3 18.11,31.11 18.47,30.74 18.47,30.69 19.06,30.1 19.06,29.37 19.02,29.33 18.91,29.33 18.91,29.34 15.86,29.34 15.54,29.65 15.54,31.32 15.29,31.57 15.29,32.28 15.56,32.55 17.85,32.55
S1_CPU_VDDQ_DDR on TOP: 38.36,31.6 38.64,31.33 38.64,30.51 37.79,29.66 37.79,28.8 37.78,28.79 37.01,28.79 37.01,28.79 35.76,28.79 35.41,28.44 35.41,28.05 35.19,27.84 34.5,27.84 34.17,28.17 34.17,28.59 34.43,28.85 34.47,28.85 35.29,29.67 35.71,29.67 35.74,29.7 35.74,31.1 36.25,31.6
S1_NVCC_BBSM_1V8 on TOP: 18.42,15.09 18,14.68 17.27,14.68 16.65,14.06 16.65,12.65 16.48,12.48 14.5,12.48 14.3,12.68 14.31,13.15 14.31,13.76 14.79,14.25 14.79,15.15 14.86,15.22 16.59,15.22 17.18,15.81 18.37,15.81 18.42,15.76
S1_VDD_SOC_0V85 on TOP: 45.12,20.56 44.61,20.05 44.61,19.01 44.56,18.96 42.88,18.96 42.27,19.57 41.13,19.57 40.95,19.74 40.95,20.23 41.53,20.81 42.22,20.81 42.6,21.19 42.6,22.64 42.45,22.79 42.45,23.32 42.68,23.55 45.78,23.55 45.98,23.35 45.98,21.19 45.65,20.86 45.27,20.86 45.12,20.71
S1_VSYS_5V on TOP: 43.67,7.93 43.46,7.73 42.55,7.73 42.1,7.28 42.1,5.82 42.09,5.82 41.84,5.57 40.81,5.57 40.79,5.59 40.43,5.59 40.29,5.72 40.29,6.08 40.5,6.23 40.52,6.23 40.87,6.23 40.93,6.28 40.93,9.2 41.83,10.11 41.83,10.18 43.09,11.44 46.08,11.44 46.12,11.4 46.12,10 45.9,9.79 45.9,9.66 45.65,9.41 45.65,9.07 45.43,8.85 44.15,8.85 43.67,8.36
S1_VSYS_5V on L4_PWR: 40.77,9.23 42.93,11.39 47.66,11.39 47.68,11.36 47.68,9.41 47.61,9.33 43.85,9.33 42.12,7.6 41.33,7.6 40.77,8.16
VLDO3_1V8 on TOP: 14.79,1.56 13.93,1.56 13.24,2.24 13.24,3.51 13.87,4.15 14.47,4.15 15.2,3.42 15.2,1.96
VMEAS_3V3 on L4_PWR: 1.08,60.52 33.79,60.52 34.67,59.64 34.67,51.83 33.25,50.42 30.73,50.42 26.68,46.37 23.45,46.37 22.06,44.98 22.06,39.33 21.58,38.85 12.65,38.85 9.69,35.88 9.69,1.7 9.02,1.04 1.19,1.04 0.57,1.65 0.57,60.01
VSD2_3V3 on TOP: 34.19,7.04 36.43,7.04 36.68,6.79 36.68,5.65 36.1,5.06 35.31,5.06 34.3,4.05 33.15,4.05 32.98,4.22 32.98,5.82
VSD2_3V3 on TOP: 66.55,28.49 69.47,28.49 69.73,28.23 69.73,27.87 69.56,27.7 66.48,27.7 66.35,27.83 66.35,28.29
VSD2_3V3 on BOTTOM: 66.46,28.36 69.87,28.36 69.99,28.24 69.99,27.84 69.86,27.71 66.4,27.71 66.32,27.79 66.32,28.22
VSD_3V3 on TOP: 31.63,5.54 32.16,5.54 34.7,8.08 36.48,8.08 36.68,8.29 36.68,8.77 36.35,9.1 34.68,9.1 34.4,8.82 33.61,8.82 32.54,7.75 32.54,7.53 31.4,6.38 31.4,5.77
VSYS_5V on TOP: 27.77,5.7 29.24,5.7 29.34,5.49 29.34,4.53 28.56,3.74 28.56,2.24 28.15,1.84 27.41,1.84 27.11,2.14 27.11,4.81 26.42,5.49 26.4,5.49 26.4,6.15 26.45,6.2 26.78,6.2 27.18,5.8 27.67,5.8
VSYS_5V on TOP: 10.19,16.92 8.77,16.92 8.53,17.16 8.53,18.1 8.64,18.22 10.5,18.22 10.67,18.04 10.67,17.41
VSYS_5V on TOP: 29.22,17.79 30.1,17.79 30.84,18.52 31.45,18.52 31.73,18.8 32.9,18.8 33.25,18.45 33.25,18.12 33.23,18.09 31.17,18.09 30.77,17.69 30.51,17.69 30.41,17.58 30.41,17.18 30.38,17.15 29.22,17.15
VSYS_5V on TOP: 26.04,15.15 26.6,15.15 26.63,15.12 26.63,14.64 26.32,14.64 25.99,14.31 25.46,14.31 25.1,14.66 25.1,15.22 25.25,15.37 25.81,15.37
VSYS_5V on TOP: 38.56,8.24 39.76,8.24 39.81,8.19 39.83,8.19 39.93,8.08 39.93,6.03 39.48,5.57 37.27,5.57 37.17,5.67 37.17,6.84
VSYS_5V on TOP: 29.83,13.47 29.24,13.47 28.76,13.95 28.76,14.23 28.5,14.49 28.17,14.49 28,14.66 28,15.2 28.05,15.25 28.35,15.25 28.68,14.92 29.19,14.92 29.95,14.15 29.95,13.6
VSYS_5V on TOP: 46.87,3.36 46.87,1.79 46.69,1.61 44.7,1.61 44.14,2.17 44.14,3.36 44.27,3.49 44.3,3.51 44.84,4.05 46.21,4.05
VSYS_5V on BOTTOM: 29.91,2.1 30.36,1.66 30.38,1.66 30.51,1.53 43.49,1.53 44.11,2.15 44.11,3.5 44.43,3.82 45.62,3.82 45.83,3.61 46.64,3.61 46.82,3.44 46.82,0.72 46.61,0.52 27.44,0.52 26.84,1.11 26.84,4.13 27.18,4.48 28.86,4.48 29.91,3.42
VSYS_5V on BOTTOM: 32.87,16.26 32.59,15.98 30.13,15.98 29.83,15.68 29.83,14.26 30,14.08 30,13.62 29.83,13.44 29.27,13.44 28.38,14.33 26.02,14.33 25.91,14.23 24.31,14.23 24.09,14.46 24.09,15.02 24.1,15.03 24.1,17.39 24.09,17.41 24.09,17.86 24.31,18.09 25.63,18.09 26.27,17.46 26.27,16.21 26.5,15.98 28.71,15.98 29.17,16.44 29.17,18.17 29.83,18.83 32.72,18.83 33.13,18.42 33.13,18.22 32.87,17.96
VSYS_5V on L3_INT_1: 46.08,6.36 46.08,4.73 46.28,4.53 46.28,2.47 45.75,1.94 43.69,1.94 43.19,2.45 43.19,3.69 41.26,5.62 41.26,6.05 37.32,9.99 24.69,9.99 24.03,10.65 24.03,14.18 25.48,15.63 38.08,15.63 44.69,9.02 44.69,7.75
VSYS_5V on L4_PWR: 24.35,13.28 22.41,15.22 22.41,21.57 22.69,21.85 32.29,21.85 33,21.14 33,15.23 32.07,14.3 32.07,13.81 31.37,13.11 31.37,11.95 31.07,11.64 24.95,11.64 24.67,11.92 24.67,12.97 24.36,13.28
VSYS_5V on L4_PWR: 37.8,7.65 37.8,7.65 37.96,7.8 40.67,7.8 40.75,7.73 40.77,7.73 41.15,7.35 43.31,7.35 44.38,6.28 46.46,6.28 47.13,5.62 47.13,3.47 46.08,2.42 41.99,2.42 40.95,3.47 38.75,3.47 37.42,4.79 37.42,7.27
N116434822 on TOP: 29.17,16.97 29.14,16.95 29.14,16.47 29.24,16.36 30.05,16.36 31.03,15.39 32.37,15.39 32.37,16.85 32.19,17.03 30.36,17.03 30.31,16.97
N116772045 on TOP: 25.71,5.19 25.71,1.58 25.81,1.48 26.57,1.48 26.68,1.58 26.68,4.91 26.17,5.42 25.94,5.42

Small or netless copper shapes (teardrops, artwork), in the pictures only: 1 on TOP

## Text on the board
Ref Des/Assembly Bottom: ASSEMBLY BOTTOM
Ref Des/Silkscreen Bottom: S/N
User.Comments: TOLERANCE +/- 0.1mm | PART NO :501-1-03450 | PART NAME : | DESIGNED FOR: | i.MX93 SOM | REV-A1 | LAYER: | ALL Dimension are in mm | 22. THIS FAB_VIAFILL.ART SHOWS LOCATIONS OF VIA_IN _PAD TO BE FILLED
Ref Des/Assembly Top: ASSEMBLY TOP
Ref Des/Silkscreen Top: C | D | 1V8 | B | 1V1 | 3V3 | POR | REQ | ON | BM0/ | STBY | 0V6 | VBUS | DN | DP | GND | TXD1 | RXD1 | TXD2 | BM1/ | RXD2 | BM3 | BM2
XSECTION_CHART: DESIGN CROSS SECTION CHART | 1-6 | *  DIELECTRIC - FR-4 2.8 MIL(+0/-0) | *  DIELECTRIC - FR-4 3 MIL(+0/-0) | *  SURFACE - AIR 0 MIL(+0/-0) | L5 L5_GND_2 PLANE - COPPER 1.2 MIL(+0/-0) | L3 L3_INT_1 CONDUCTOR - COPPER 1.2 MIL(+0/-0) | L6 BOTTOM CONDUCTOR - COPPER 1.38 MIL(+0/-0) | L2 L2_GND_1 PLANE - COPPER 1.2 MIL(+0/-0) | L1 TOP CONDUCTOR - COPPER 1.38 MIL(+0/-0) | *  DIELECTRIC - FR-4 42.9 MIL(+0/-0) | L4 L4_PWR PLANE - COPPER 1.2 MIL(+0/-0) | ___________________________ | TOTAL THICKNESS 62.06 MIL | CORE | 3.49 | 3.97 | 4.15 | 0.02 | DETAIL A
DIMENSION: X(0,0)
User.10: PANEL FIDUCIAL | (TOP AND BOTTOM) | (3 PLACES) | TOOLING HOLES 3.20 MM | (4 PLACES)
User.12: PANEL_TOP | ALL DIMENSIONS ARE IN MILLIMETERS | TOLERANCE + / - 0.1MM
User.13: PANEL_BOTTOM
User.18: L6_BOTTOM | L3_IN1 | L1_TOP | 4.5 | 4.4 | 50 | 4.6 | 3.4 | 85 | 3.2 | 4 | 5.3 | 90 | 2.9 | 5.6 | 8.1 | 100
User.24: TOP
User.25: L4_PWR
User.26: BOTTOM
User.27: L3_SIG
User.29: L5_GND_2
User.30: L2_GND1
User.45: B | A | D | C | 1 | 2 | 3 | 4 | 5 | 6 | 7 | 8 | - | BOTTOM SILK | BOTTOM SOLDER | ASSEMBLY | DRAWING | DIMENSIONS ARE IN METRICS | DO NOT SCALE DRAWING PRINT | TOLERANCE ARE | UNLESS OTHERWISE SPECIFIED | SHEET : 1OF3 | TOP SOLDER | TOP SILK | FAB DRAWING | UPDATED MANUALLY | NEEDS TO BE | +0.1 | VVDN TECHNOLOGIES PVT.LTD. | FAB_ | 501-1-03450_A1.ZIP CONSISTS OF | PCB PRIMARY SIDE | MAXIMUM HEIGHT 15.5 MM | PCB SECONDARY SIDE | MAXIMUM HEIGHT 3 MM | PCB Thickness 1.5 mm | REV | A1 | 08-05-2024 | DATE | INITIAL RELEASE | REVISION NOTES | TITLE: | ASY NUMBER: | i.MX93 SOM | PCBA ASSEMBLY DRAWING | VVDN_TECHNOLOGIES.PVT.LTD | PCB_DESIGNER | SURYAA | 501-1-03450 | ASY_501-1-03450_A1.ZIP CONSISTS OF FOLLOWING ASSEMBLY DATA | PMT_ | PMB_ | PNP_ | 501-1-03450_A1 | .ART -  TOP PASTE | .ART -  BOTTOM PASTE | .XLS -  PICK AND PLACE DATA | 10) | 12) | 13) | 14) | 15) | 11) | 18) | 19) | 16) | 17) | 20) | 3) | 4) | 5) | 6) | 8) | 9) | 7) | NOTES: UNLESS OTHERWISE SPECIFIED | MATERIAL: UL RECOGNIZED COMPONENT ZPMV2, 94V-1 MINIMUM. | FINISH | MATERIAL | THRU L6_ BOTTOM_501-1-03450_A1.ART | APPLY LPI GREEN COLOR SOLDER MASK TO INDICATED SIDES OVER BARE COPPER. | REFER TO PANEL DRAWING FOR PANEL DETAILS. | THERE ARE IMPEDANCE CONTROLED SIGNALS RUNNING INSIDE BOARD. | LAYER TO LAYER REGISTRATION SHALL BE WITHIN 0.08 MM. | VENDOR SHOULD NOT MODIFY ARTWORK EXCEPT FOR PROCESS CONTROL. | ALL COMPONENTS AND MATERIAL USED ARE PB FREE AND ROHS COMPLAINT | SILKSCREEN SHOULD BE WHITE, NON-CONDUCTIVE EPOXY INK. | BOARD THICKNESS WHICH EVER MENTIONED IS WITH PLATING. | ONLY MARK DATE CODE, DON'T MARK VENDOR LOGO. | FABRICATE TO THE REQUIREMENTS OF IPC-A-600. | HANDLE, PACKAGE, AND SHIP CAREFULLY THAT TO ENSURE NO DAMAGE. | ETCH PER GERBER FILES L1_TOP_501-1-03450_A1.ART | LABELING SHALL NOT BE PLACED OVER EXPOSED COPPER. | BOARD SHOULD BE 100% ELECTRICALLY TESTED FOR OPEN AND SHORT CIRCUIT. | ALL HOLE DIAMETER TO BE  +/-0.075mm  UNLESS OTHERWISE SPECIFIED. | ALL HOLE DIAMETERS  ARE FINISHED SIZE. | BOW AND TWIST SHALL NOT EXCEED 0.75% OR AS PER  IPC APPLICABLE CLAUSE. | MANDATORY BAKE REQUIREMENT MUST BE MENTIONED IN THE PACKING BOX. | GOLD PLATING 0.076-0.2 MICRONS THICK | ENIG (ELECTROLESS NICKEL IMMERSION GOLD) AFTER COPPER PLATING, | PLATE ELECTROLESS NICKEL 1-4 MICRONS THICK FOLLOWED BY AN IMMERSION | 61.11 | dia | 2.70 | 26.73 | 26.55 | (4X) | 4.01 | 34.33 | 73.74 | 19.01 | R0.75 | TYP | 1.60 | FAB NUMBER: | 701-1-04331 | 6) ASSEMBLY SHALL BE ELCECTRICALLY TESTED. | NOTES:          UNLESS OTHERWISE SPECIFIED. | 5) APERTURES MAY BE MODIFIED TO BEST FIT VVDN REQUIREMENT. | 1) SOLDER AND ASSEMBLE AS PER INDUSTRY WORKMANSHIP STANDARDS. | 8) "FIDUCIAL'S  WILL NOT BE THRU OPEN, IT SHOULD BE HALFETCH". | 2) LABELS SHALL NOT TO BE PLACED OVER EXPOSED COPPER AND METAL. | 7) STICK TO THE BACKING REQUIREMENT AS PER CLASS RECOMMENEDATION. | CAUTION :       COMPONENTS ARE SUBJECT TO DAMAGE BY STATIC ELECTRICITY. | 3) SOLDER PASTE TOOLING SHOULD BE MADE USING PMT_501-1-02988_A1_PMT.ART FOR PRIMARY SIDE. | 4) SOLDER PASTE TOOLING SHOULD BE MADE USING PMB_501-1-02988_A1_PMB.ART FOR SECONDARY SIDE. | FIGURE | FINISHED_SIZE | 8.0 | 10.0 | 40.0 | 106.0 | 33.4 | 66.9 | DRILL CHART: TOP to BOTTOM | ALL UNITS ARE IN MILS | TOLERANCE_DRILL | +0.0/-0.0 | +0.0/-8.0 | +0.0/-10.0 | +3.0/-3.0 | +1.0/-1.0 | +4.0/-4.0 | PLATED | NON-PLATED | QTY | 28 | 1137 | 51 | 1230 | TOTAL HOLES: | PCB FABRICATION DRAWING | IPC_ | L3_SIG1_501-1-03450_A1.ART- | L5_PWR_501-1-03450_A1.ART- | L2_GND_501-1-03450_A1.ART - | L1_TOP_ | L4_SIG2_501-1-03450_A1.ART - | SST_ | RFQ_ | SMB_ | SMT_ | L6_BOTTOM_501-1-03450_A1.ART - | SSB_ | ART_APER_ | ART_PARAM_ | CUTOUT_ | ROU_ | NC_PARAM_ | DRL_1-6_ | NC_TOOLS_ | PNL_ | .IPC -     IPC 365 NETLIST | .ART -     SILKSCREEN TOP | .ART -     SOLDERMASK BOTTOM | .ART -     SOLDERMASK TOP | .ART -     SILKSCREEN BOTTOM | .PDF -     FABRICATION DRAWING | .ART -     PASTEMASK TOP | .ART -     PASTEMASK BOTTOM | .ART -     PANEL DRAWING | .ROU -     ROUTE FILE | .ART -    CUTOUT | .ART -     LAYER 01 (TOP SIDE) | .DRL -     NC DRILL | .TXT -     NC TOOLS REPORT | .TXT -     NC PARAMETERS | .TXT -     ART PARAMETER | .TXT -     ART APERTURE | LAYER 03 (SIGNAL SIDE1) | LAYER 05 (POWER PLANE) | LAYER 02 (GROUND PLANE) | LAYER 04 (SIGNAL SIDE2) | LAYER 06 (BOTTOM SIDE) | DESIGN ORIGIN (0,0)
